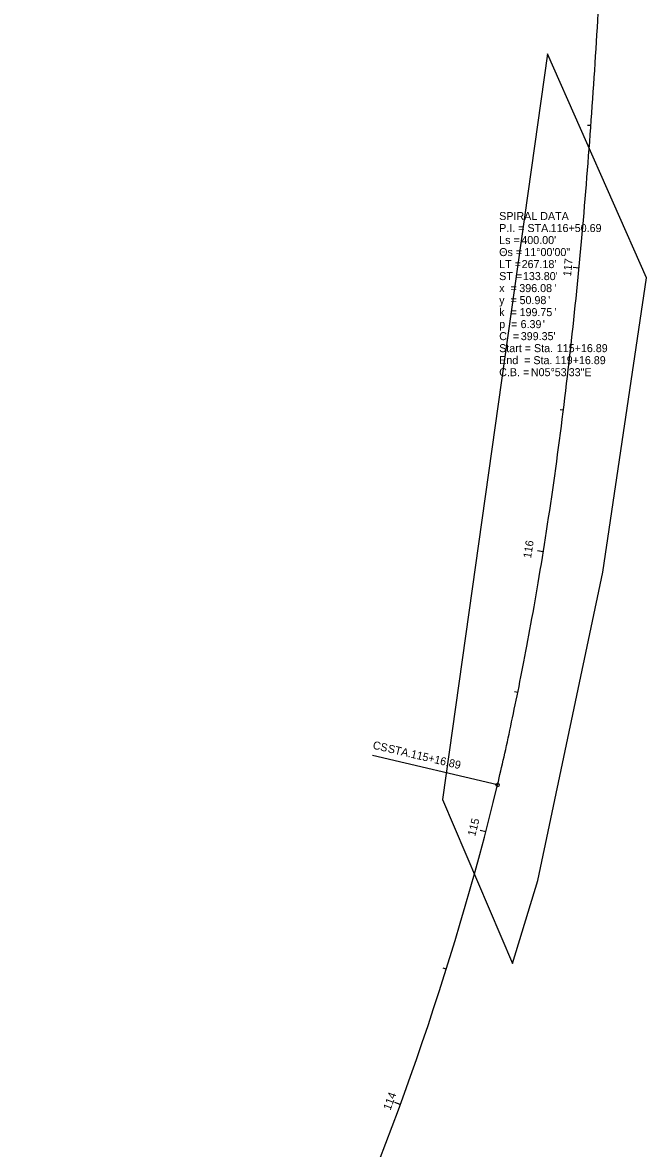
# Model space of a CAD drawing. Extents: x 1832834 to 1833221, y 712492 to 713942.
# Drawn here: x 1832992.9 to 1833211.2, y 712885.7 to 713279.5 of the extents above; entities that cross this region are included whole.
import ezdxf

# ---------------------------------------------------------------- set-up
doc = ezdxf.new("R2010")
doc.units = 0
for name, color, linetype in [('DT_X_Break_Line', 7, 'Continuous'), ('DT_X_Contour_Minor', 7, 'Continuous'), ('DT_X_Spot_Elev', 7, 'Continuous'), ('DT_X_Triangles', 7, 'Continuous'), ('DT_X_Void', 7, 'Continuous'), ('PV_X_EOP', 7, 'Continuous')]:
    doc.layers.add(name, color=color, linetype=linetype)

msp = doc.modelspace()

# ---------------------------------------------------------------- linework, layer by layer
at = {"layer": 'DT_X_Contour_Minor'}
msp.add_arc((1832147.05, 713259.75), 1041.74, 324.28906, 346.28909, dxfattribs=at)
msp.add_open_spline([(1833159.11, 713012.83), (1833160.63, 713019.32), (1833163.56, 713032.33), (1833168.93, 713058.45), (1833174.81, 713091.27), (1833180.64, 713130.85), (1833185.41, 713170.56), (1833189.26, 713210.38), (1833192.35, 713250.26), (1833194.83, 713290.19), (1833196.84, 713330.14), (1833198.26, 713363.44), (1833199.33, 713390.08), (1833199.84, 713403.41), (1833200.1, 713410.07)], degree=3, dxfattribs=at)
at = {"layer": 'DT_X_Spot_Elev'}
msp.add_line((1833159.11, 713012.83), (1833115.3, 713023.13), dxfattribs=at)
msp.add_circle((1833159.11, 713012.83), 0.6, dxfattribs=at)
at = {"layer": 'DT_X_Triangles'}
msp.add_lwpolyline([(1833139.83, 713007.71), (1833164.34, 712950.39), (1833173.21, 712979.46), (1833195.91, 713087.21), (1833211.21, 713190.19), (1833176.61, 713268.47)], close=True, dxfattribs=at)
at = {"layer": 'DT_X_Void'}
for p, q in [((1833191.76, 713243.4), (1833190.56, 713243.48)), ((1833187.6, 713193.57), (1833185.61, 713193.76)), ((1833182.15, 713143.87), (1833180.96, 713144.02)), ((1833175.1, 713094.37), (1833173.13, 713094.69)), ((1833166.18, 713045.18), (1833165.01, 713045.42)), ((1833154.97, 712996.46), (1833153.03, 712996.96)), ((1833141.18, 712948.4), (1833140.03, 712948.76)), ((1833125.09, 712901.07), (1833123.22, 712901.75))]:
    msp.add_line(p, q, dxfattribs=at)

# ---------------------------------------------------------------- texts
at = {"layer": 'DT_X_Break_Line'}
for s, p in [('SPIRAL DATA', (1833159.68, 713210.39)), ('P.I. = STA. ', (1833159.68, 713206.19)), ('116+50.69', (1833177.67, 713206.19)), ('Ls = ', (1833159.68, 713201.99)), ("400.00'", (1833167.43, 713201.99)), ('Θs = ', (1833159.68, 713197.79)), ('11°00\'00"', (1833168.46, 713197.79)), ('LT = ', (1833159.68, 713193.59)), ("267.18'", (1833167.53, 713193.59)), ('ST = ', (1833159.68, 713189.39)), ("133.80'", (1833167.98, 713189.39)), ('x  = ', (1833159.68, 713185.19)), ('396.08', (1833166.71, 713185.19)), ("'", (1833178.96, 713185.19)), ('y  = ', (1833159.68, 713180.99)), ('50.98', (1833166.81, 713180.99)), ("'", (1833176.83, 713180.99)), ('k  = ', (1833159.68, 713176.79)), ('199.75', (1833166.81, 713176.79)), ("'", (1833179.06, 713176.79)), ('p  = ', (1833159.68, 713172.59)), ('6.39', (1833167.16, 713172.59)), ("'", (1833174.94, 713172.59)), ('C  = ', (1833159.68, 713168.39)), ("399.35'", (1833167.23, 713168.39)), ('Start = Sta. ', (1833159.68, 713164.19)), ('115+16.89', (1833179.83, 713164.19)), ('End  = Sta. ', (1833159.68, 713159.99)), ('119+16.89', (1833179.14, 713159.99)), ('C.B. = ', (1833159.68, 713155.79)), ('N05°53\'33"E', (1833170.75, 713155.79))]:
    msp.add_text(s, height=2.8, dxfattribs=at).set_placement(p)
at = {"layer": 'DT_X_Spot_Elev'}
for s, p in [('CS', (1833115.25, 713025.55)), (' STA. ', (1833119.49, 713024.55)), ('115+16.89', (1833128.56, 713022.42))]:
    msp.add_text(s, height=2.8, rotation=346.7731, dxfattribs=at).set_placement(p)
at = {"layer": 'DT_X_Void'}
for s, rotation, p in [('117', 84.5391, (1833184.8, 713190.58)), ('116', 80.8693, (1833170.8, 713091.97)), ('115', 75.3601, (1833151.26, 712994.71))]:
    msp.add_text(s, height=2.8, rotation=rotation, dxfattribs=at).set_placement(p)
at = {"layer": 'PV_X_EOP'}
msp.add_text('114', height=2.8, rotation=69.8601, dxfattribs=at).set_placement((1833121.62, 712898.85))

doc.saveas('drawing.dxf')
